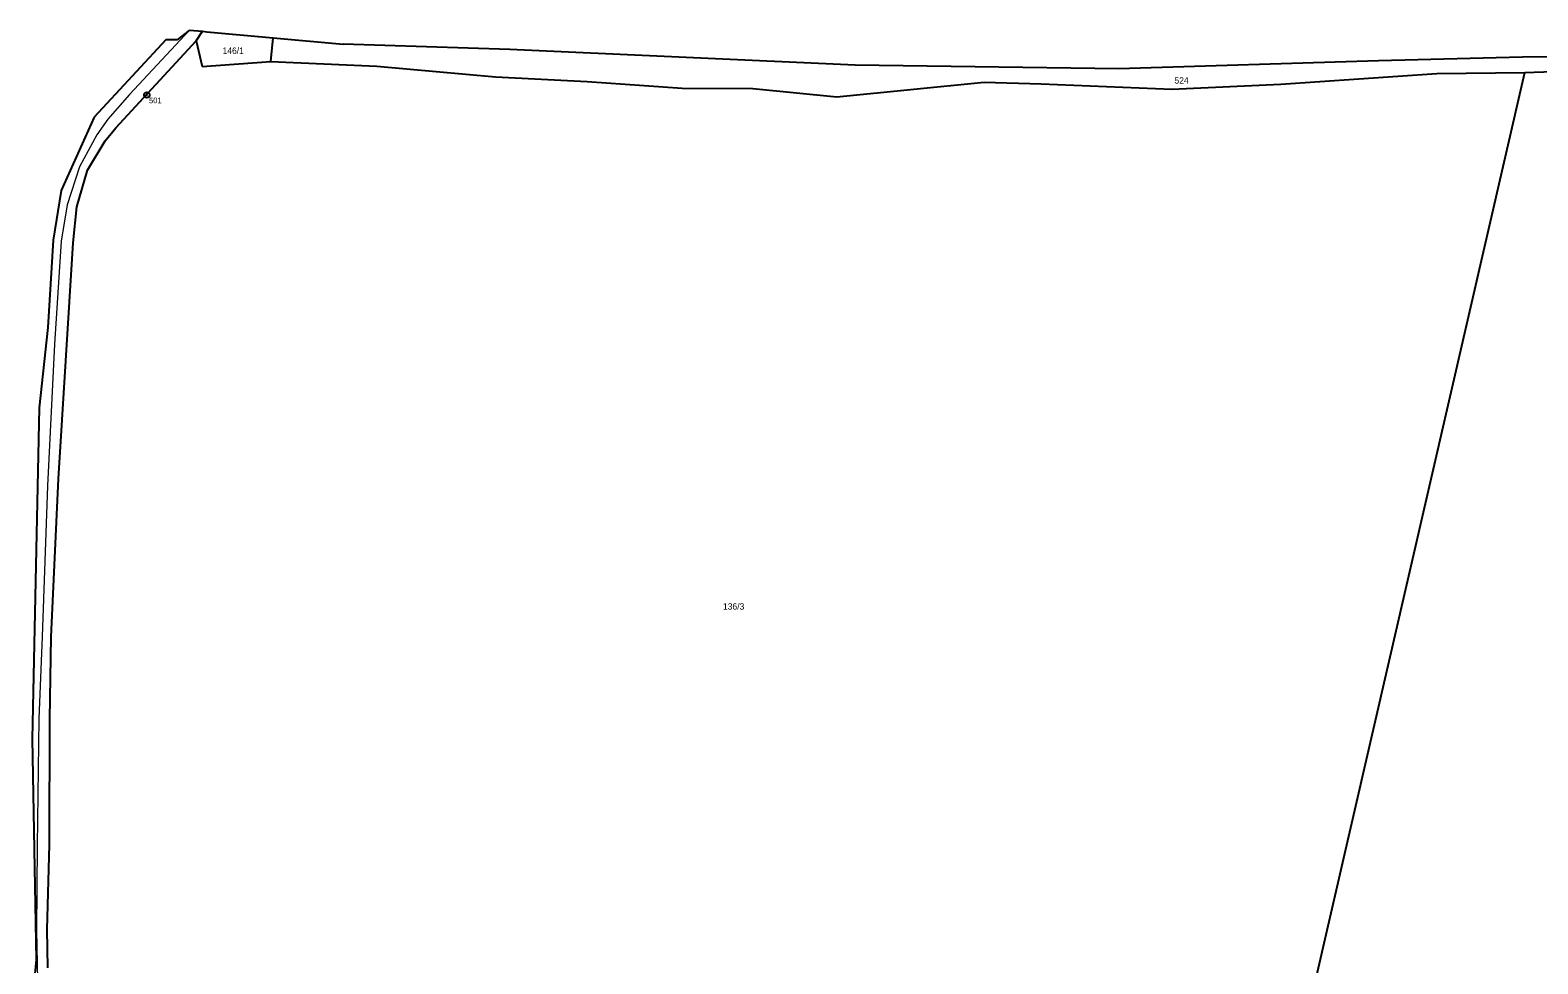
# Model space of a CAD drawing. Extents: x -885985 to -883535, y -1030025 to -1027941.
# Drawn here: x -885769.9 to -885368.3, y -1028300.8 to -1028052.1 of the extents above; entities that cross this region are included whole.
import ezdxf
from ezdxf.enums import TextEntityAlignment as Align

# ---------------------------------------------------------------- set-up
doc = ezdxf.new("R2010")
doc.units = 0
doc.header["$LTSCALE"] = 0.68
for name, color, linetype, lineweight in [('1', 7, 'Continuous', 25), ('4', 7, 'Continuous', 13), ('8', 7, 'Continuous', 25)]:
    doc.layers.add(name, color=color, linetype=linetype, lineweight=lineweight)
doc.layers.add('2', color=7, linetype='Continuous')

msp = doc.modelspace()

# ---------------------------------------------------------------- linework, layer by layer
at = {"layer": '1'}
for p, q in [((-885727.48, -1028052.14), (-885730.73, -1028054.71)), ((-885727.48, -1028052.14), (-885724.03, -1028052.45)), ((-885725.7, -1028054.96), (-885724.03, -1028052.45)), ((-885724.03, -1028052.45), (-885722.83, -1028052.56)), ((-885722.83, -1028052.56), (-885705.2, -1028054.15)), ((-885705.77, -1028060.46), (-885705.2, -1028054.15)), ((-885705.2, -1028054.15), (-885686.54, -1028055.84)), ((-885733.82, -1028054.71), (-885752.9, -1028075.33)), ((-885747.06, -1028078.11), (-885725.7, -1028054.96)), ((-885730.73, -1028054.71), (-885733.82, -1028054.71)), ((-885725.7, -1028054.96), (-885724.08, -1028061.8)), ((-885642.16, -1028057.26), (-885686.54, -1028055.84)), ((-885550.16, -1028061.48), (-885642.16, -1028057.26)), ((-885724.08, -1028061.8), (-885705.77, -1028060.46)), ((-885705.77, -1028060.46), (-885677.54, -1028061.71)), ((-885677.54, -1028061.71), (-885645.96, -1028064.6)), ((-885479.89, -1028062.42), (-885550.16, -1028061.48)), ((-885410.76, -1028060.33), (-885479.89, -1028062.42)), ((-885372.4, -1028059.37), (-885410.76, -1028060.33)), ((-885337.26, -1028058.82), (-885372.4, -1028059.37)), ((-885371.7, -1028063.43), (-885325.5, -1028061.8)), ((-885645.96, -1028064.6), (-885621.53, -1028065.8)), ((-885621.53, -1028065.8), (-885596.19, -1028067.58)), ((-885555, -1028069.87), (-885515.73, -1028065.95)), ((-885515.73, -1028065.95), (-885500.62, -1028066.43)), ((-885500.62, -1028066.43), (-885465.81, -1028067.85)), ((-885465.81, -1028067.85), (-885436.77, -1028066.55)), ((-885436.77, -1028066.55), (-885395.15, -1028063.64)), ((-885412.58, -1028240.57), (-885371.7, -1028063.43)), ((-885395.15, -1028063.64), (-885371.7, -1028063.43)), ((-885596.19, -1028067.58), (-885577.39, -1028067.68)), ((-885577.39, -1028067.68), (-885555, -1028069.87)), ((-885752.9, -1028075.33), (-885761.65, -1028094.86)), ((-885749.98, -1028081.6), (-885747.06, -1028078.11)), ((-885754.69, -1028089.44), (-885749.98, -1028081.6)), ((-885757.45, -1028099.22), (-885754.69, -1028089.44)), ((-885761.65, -1028094.86), (-885763.81, -1028108.02)), ((-885758.48, -1028108.73), (-885757.45, -1028099.22)), ((-885763.81, -1028108.02), (-885765.22, -1028131.3)), ((-885762.37, -1028171.61), (-885758.48, -1028108.73)), ((-885765.22, -1028131.3), (-885767.5, -1028152.72)), ((-885767.5, -1028152.72), (-885769.35, -1028240.86)), ((-885764.3, -1028213.66), (-885762.37, -1028171.61)), ((-885764.71, -1028235.49), (-885764.3, -1028213.66)), ((-885764.79, -1028268.99), (-885764.71, -1028235.49)), ((-885769.35, -1028240.86), (-885768.32, -1028299.71)), ((-885453.46, -1028417.7), (-885412.58, -1028240.57)), ((-885765.44, -1028291.63), (-885764.79, -1028268.99)), ((-885765.26, -1028301.8), (-885765.44, -1028291.63)), ((-885768.32, -1028299.71), (-885769.93, -1028315.6))]:
    msp.add_line(p, q, dxfattribs=at)
at = {"layer": '4'}
for p, q in [((-885727.48, -1028052.14), (-885743.46, -1028069.27)), ((-885743.46, -1028069.27), (-885749.23, -1028075.86)), ((-885749.23, -1028075.86), (-885752.19, -1028080.02)), ((-885752.19, -1028080.02), (-885756.8, -1028088.49)), ((-885756.8, -1028088.49), (-885760.04, -1028098.63)), ((-885760.04, -1028098.63), (-885761.7, -1028108.36)), ((-885761.7, -1028108.36), (-885763.4, -1028135.77)), ((-885763.4, -1028135.77), (-885765.27, -1028173.46)), ((-885765.27, -1028173.46), (-885766.75, -1028213.61)), ((-885766.75, -1028213.61), (-885767.6, -1028235.5)), ((-885767.6, -1028235.5), (-885768.1, -1028269.24)), ((-885768.1, -1028269.24), (-885768.24, -1028291.78)), ((-885768.24, -1028291.78), (-885767.81, -1028314.94))]:
    msp.add_line(p, q, dxfattribs=at)
at = {"layer": '8'}
for radius in [0.75, 0.03]:
    msp.add_circle((-885738.85, -1028069.4098), radius, dxfattribs=at)

# ---------------------------------------------------------------- texts
at = {"layer": '2'}
for s, p in [('146/1', (-885718.68, -1028058.455)), ('524', (-885465.08, -1028066.365)), ('136/3', (-885585.36, -1028206.435))]:
    msp.add_text(s, height=1.7, dxfattribs=at).set_placement(p)
at = {"layer": '8'}
msp.add_text('501', height=1.5, dxfattribs=at).set_placement((-885734.923, -1028071.592), align=Align.RIGHT)

doc.saveas('drawing.dxf')
